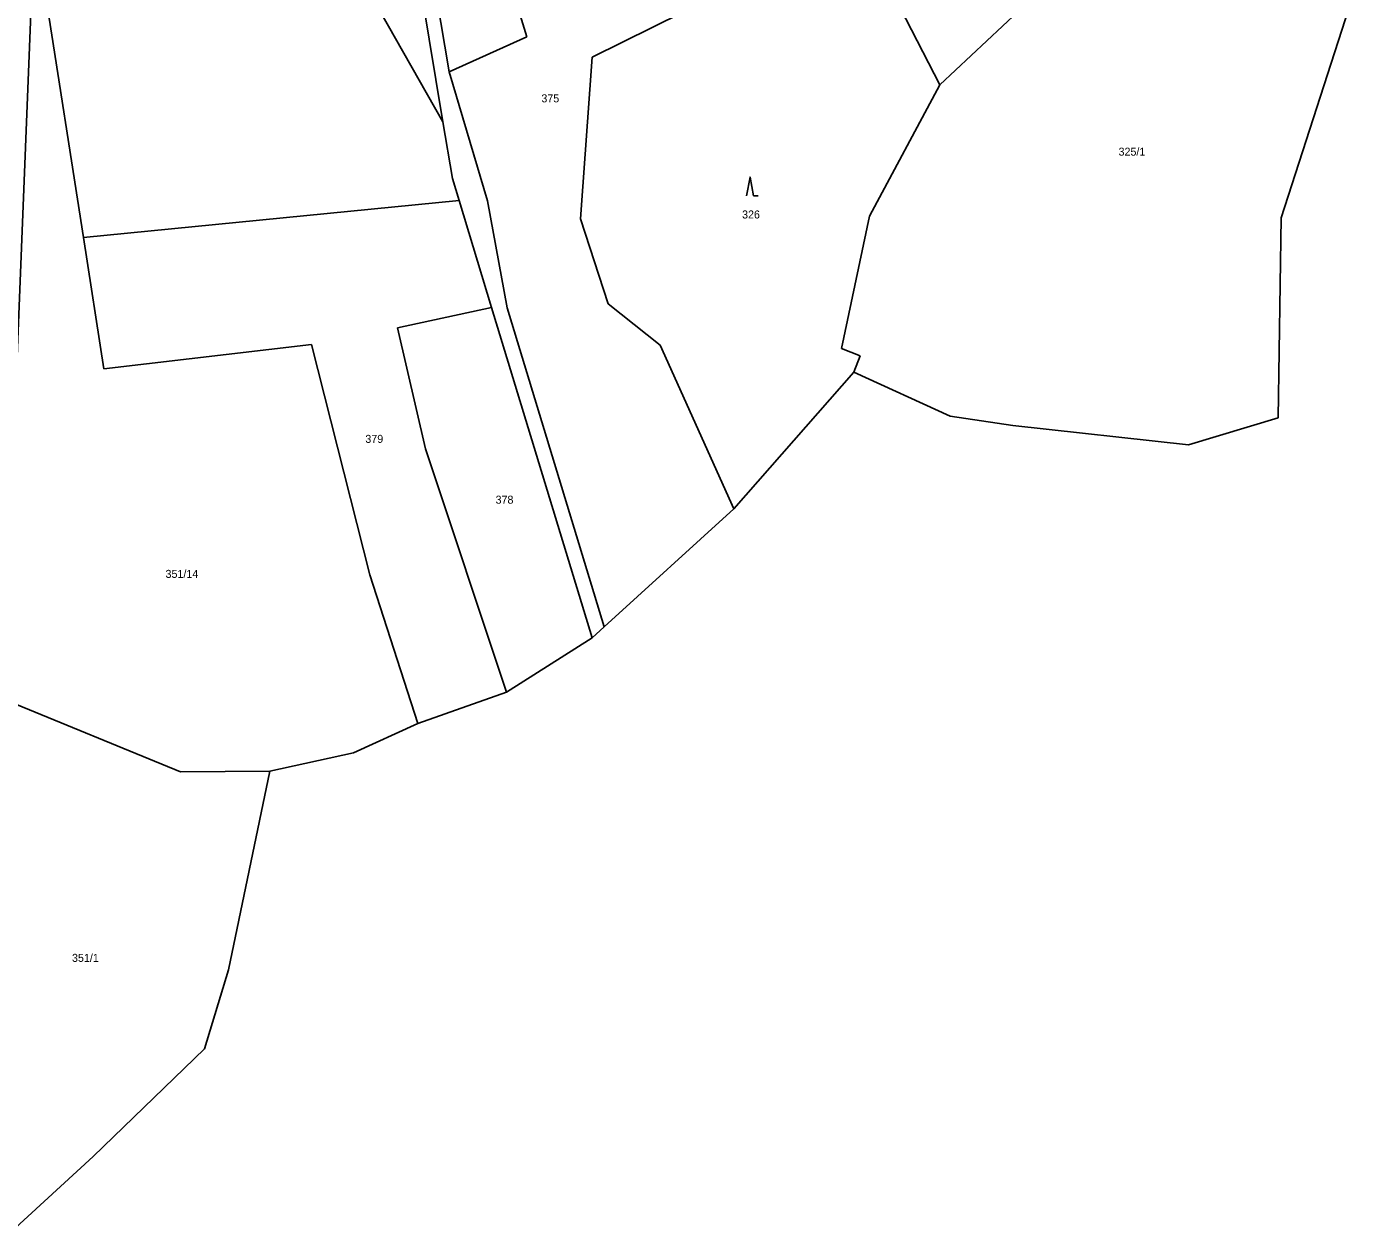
# Model space of a CAD drawing. Extents: x -664548 to -662415, y -1069720 to -1068208.
# Drawn here: x -663522.5 to -663239.8, y -1069653.8 to -1069397.8 of the extents above; entities that cross this region are included whole.
import ezdxf

# ---------------------------------------------------------------- set-up
doc = ezdxf.new("R2010")
doc.units = 0
doc.header["$LTSCALE"] = 0.68
doc.layers.add('1', color=7, linetype='Continuous', lineweight=25)
doc.layers.add('3', color=7, linetype='Continuous', lineweight=25)
doc.layers.add('2', color=7, linetype='Continuous')

msp = doc.modelspace()

# ---------------------------------------------------------------- linework, layer by layer
at = {"layer": '1'}
for p, q in [((-663416.26, -1069400.01), (-663439.87, -1069321.52)), ((-663445.32, -1069350.54), (-663434.06, -1069418.05)), ((-663441.76, -1069353.53), (-663432.72, -1069407.43)), ((-663527.43, -1069540.73), (-663520.83, -1069375.97)), ((-663520.83, -1069375.97), (-663510.43, -1069442.65)), ((-663456.74, -1069378.18), (-663434.06, -1069418.05)), ((-663345.95, -1069376.22), (-663402.37, -1069404.33)), ((-663328.48, -1069410.22), (-663345.95, -1069376.22)), ((-663302.13, -1069385.5), (-663328.48, -1069410.22)), ((-663239.78, -1069388.33), (-663255.97, -1069438.48)), ((-663432.72, -1069407.43), (-663416.26, -1069400.01)), ((-663402.37, -1069404.33), (-663404.82, -1069438.7)), ((-663328.48, -1069410.22), (-663343.44, -1069438.08)), ((-663434.06, -1069418.05), (-663432.05, -1069430.09)), ((-663432.05, -1069430.09), (-663430.62, -1069434.79)), ((-663510.43, -1069442.65), (-663430.62, -1069434.79)), ((-663430.62, -1069434.79), (-663423.74, -1069457.47)), ((-663343.44, -1069438.08), (-663349.42, -1069466.21)), ((-663404.82, -1069438.7), (-663398.94, -1069456.73)), ((-663255.97, -1069438.48), (-663256.62, -1069480.91)), ((-663510.43, -1069442.65), (-663506.08, -1069470.51)), ((-663443.7, -1069461.81), (-663423.74, -1069457.47)), ((-663423.74, -1069457.47), (-663402.38, -1069527.67)), ((-663398.94, -1069456.73), (-663387.93, -1069465.53)), ((-663443.7, -1069461.81), (-663437.78, -1069487.55)), ((-663506.08, -1069470.51), (-663462.02, -1069465.38)), ((-663462.02, -1069465.38), (-663449.6, -1069514.29)), ((-663387.93, -1069465.53), (-663372.27, -1069500.27)), ((-663349.42, -1069466.21), (-663345.39, -1069467.8)), ((-663346.8, -1069471.26), (-663345.39, -1069467.8)), ((-663346.8, -1069471.26), (-663372.27, -1069500.27)), ((-663326.3, -1069480.6), (-663346.8, -1069471.26)), ((-663312.97, -1069482.55), (-663326.3, -1069480.6)), ((-663437.78, -1069487.55), (-663420.56, -1069539.24)), ((-663399.78, -1069525.31), (-663372.27, -1069500.27)), ((-663449.6, -1069514.29), (-663439.39, -1069545.91)), ((-663402.38, -1069527.67), (-663399.78, -1069525.31)), ((-663402.38, -1069527.67), (-663420.56, -1069539.24)), ((-663420.56, -1069539.24), (-663433.56, -1069543.85)), ((-663527.43, -1069540.73), (-663489.83, -1069556.13)), ((-663433.56, -1069543.85), (-663439.39, -1069545.91)), ((-663439.39, -1069545.91), (-663453.05, -1069552.12)), ((-663453.05, -1069552.12), (-663470.83, -1069556.01)), ((-663489.83, -1069556.13), (-663470.83, -1069556.01)), ((-663470.83, -1069556.01), (-663479.64, -1069598.18)), ((-663479.64, -1069598.18), (-663484.69, -1069614.96)), ((-663484.69, -1069614.96), (-663508.35, -1069637.87)), ((-663508.35, -1069637.87), (-663525.71, -1069653.77))]:
    msp.add_line(p, q, dxfattribs=at)
for points in [[(-663432.72, -1069407.43), (-663424.59, -1069434.81), (-663420.44, -1069457.55), (-663399.78, -1069525.31)], [(-663256.62, -1069480.91), (-663275.65, -1069486.69), (-663312.97, -1069482.55)]]:
    msp.add_lwpolyline(points, dxfattribs=at)
at = {"layer": '3'}
msp.add_line((-663368.06, -1069433.79), (-663367.064, -1069433.79), dxfattribs=at)
msp.add_lwpolyline([(-663368.06, -1069433.79), (-663368.81, -1069429.79), (-663369.56, -1069433.79)], dxfattribs=at)

# ---------------------------------------------------------------- texts
at = {"layer": '2'}
for s, p in [('375', (-663413.15, -1069413.925)), ('325/1', (-663290.52, -1069425.245)), ('326', (-663370.51, -1069438.594)), ('379', (-663450.55, -1069486.265)), ('378', (-663422.88, -1069499.185)), ('351/14', (-663493, -1069514.945)), ('351/1', (-663512.87, -1069596.515))]:
    msp.add_text(s, height=1.7, dxfattribs=at).set_placement(p)

doc.saveas('drawing.dxf')
